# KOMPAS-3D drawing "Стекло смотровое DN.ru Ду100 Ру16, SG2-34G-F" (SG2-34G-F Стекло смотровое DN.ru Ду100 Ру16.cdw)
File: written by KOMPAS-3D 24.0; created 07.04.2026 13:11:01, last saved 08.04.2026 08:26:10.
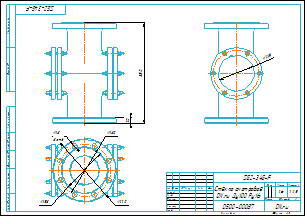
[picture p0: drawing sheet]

Document properties: Автор: Main; Форматы листов документа: A3; Полное имя файла: SG2-34G-F Стекло смотровое DN.ru Ду100 Ру16.m3d; Масса: 26; Наименование: Стекло смотровое DN.ru Ду100 Ру16; Количество листов документа: 1; Примечание: D500-00087

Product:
- Part/product: Стекло смотровое DN.ru Ду100 Ру16  | designation SG2-34G-F
    Масса: 26
    Раздел спецификации: Прочие изделия
    Примечание: D500-00087

Views: Проекционный вид 3
Referenced files in D:\DN.ru Аутсерс\Стекло смотровое DN.ru\Стекло смотровое DN.ru SG2-34G-F тип В ГОСТ 21836-2021 Ду100 Ру16, углеродистая сталь, фланцевое\: SG2-34G-F тип В Стекло смотровое DN.ru Ду100 Ру16.m3d, SG2-34G-F тип ВСтекло смотровое DN.ru Ду100 Ру16.cdw, SG2-34G-F Стекло смотровое DN.ru Ду100 Ру16.m3d
Referenced files in D:\DN.ru Аутсерс\Стекло смотровое DN.ru\SG2-34G-F Стекло смотровое DN.ru Ду100 Ру16\: SG2-34G-F Стекло смотровое DN.ru Ду100 Ру16.m3d
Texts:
  SG2-34G-F
  Стекло смотровое
  DN.ru Ду100 Ру16
  Стекло смотровое DN.ru Ду100 Ру16
  SG2-34G-F Стекло смотровое DN.ru Ду100 Ру16
Dimensions and other numbers on the sheet: 0; 3; 4; 125; 1:2,5; 1; 2; 26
